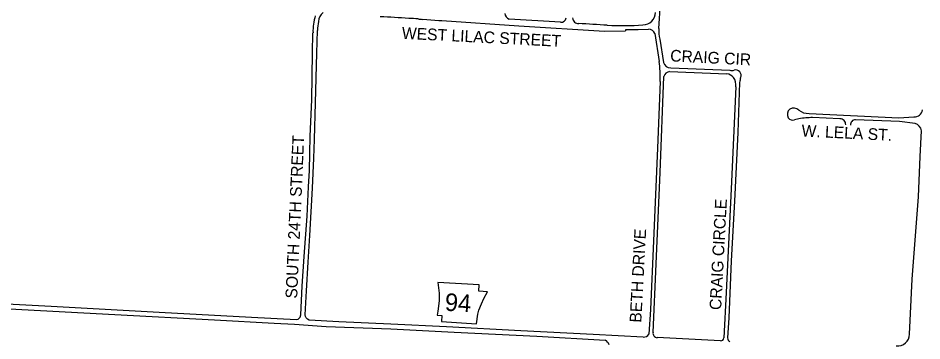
# Model space of a CAD drawing. Extents: x 0 to 712119, y 0 to 761125.
# Drawn here: x 676756 to 680612, y 727224 to 728604 of the extents above; entities that cross this region are included whole.
import ezdxf

# ---------------------------------------------------------------- set-up
doc = ezdxf.new("R2010")
doc.units = 0
for name, color, linetype in [('HWY signs', 7, 'Continuous'), ('PAVED ROADS', 7, 'Continuous'), ('street names', 7, 'Continuous')]:
    doc.layers.add(name, color=color, linetype=linetype)

msp = doc.modelspace()

# ---------------------------------------------------------------- linework, layer by layer
at = {"layer": 'HWY signs'}
msp.add_lwpolyline([(678711.4, 727298), (678717.8, 727338.3), (678722.5, 727356.1), (678732.8, 727382.8), (678743.5, 727405.2), (678758.3, 727434.3), (678721.3, 727436.5), (678723, 727463.9), (678547.5, 727474.5), (678553, 727428.9), (678552.4, 727395.8), (678546.9, 727351.5), (678543.9, 727334), (678564.1, 727332.7), (678562.6, 727306.9)], close=True, dxfattribs=at)
at = {"layer": 'PAVED ROADS'}
for points in [[(679495.5, 728670), (679495.5, 728667.5), (679489, 728559.5)], [(678482.5, 728598.5), (678551.5, 728594), (678563.5, 728593)], [(678563.5, 728593), (678892.5, 728570.5), (679258.5, 728548.5), (679348, 728550)], [(679069.6, 728585.9), (678851.9, 728599.7), (678851.9, 728599.7)], [(676708, 727383.5), (676897.5, 727373), (677358, 727347.5), (677751.5, 727325.5), (677944.5, 727315.5), (677951, 727317.5), (677955.5, 727321), (677960, 727326.5), (677962.5, 727336.5), (677969, 727458), (677977, 727585.5), (677990, 727757), (677995, 727883.5), (677999, 727952), (678001.5, 728025.5), (678003, 728099), (678009.5, 728254), (678012.5, 728455.5), (678014.5, 728541)], [(679423, 727240.5), (679210, 727251.5), (678901.5, 727267), (678584, 727284), (678346.5, 727295.5), (678125, 727306.5), (677998.5, 727313), (677991.5, 727317), (677985.5, 727322.5), (677982.1, 727328.6), (677981, 727336), (677987.5, 727438), (677994.5, 727561), (678000.8, 727674.7), (678012.2, 727876.7), (678017.5, 728005.6), (678021.1, 728085.3), (678025, 728241.1), (678030.2, 728454.1), (678033.7, 728550.7)], [(679401, 728555.5), (679446, 728556)], [(679472, 728537.5), (679490.5, 728419)], [(679493.4, 728513.7), (679510.3, 728414.5)], [(679540.5, 728391), (679792.6, 728381.1)], [(679464.9, 727260.6), (679477.7, 727554.1), (679495.8, 727944.7), (679511.6, 728354.4)], [(679535.8, 728375.2), (679779.8, 728365.8)], [(679495.4, 728333.4), (679483.9, 728047.8), (679466.3, 727652.4), (679454.1, 727359.2), (679447.2, 727254)], [(679817.6, 728309.8), (679798.5, 727874.1), (679777.6, 727432), (679766.9, 727237.3)], [(679834.5, 728328.5), (679827.1, 728114.7), (679812, 727821), (679799, 727567), (679788, 727323), (679783, 727237.5)], [(680130.4, 728196.3), (680513, 728177.5), (680577.5, 728181.5)], [(680087.5, 728173.5), (680069, 728169.5)], [(680261.9, 728173.2), (680145.5, 728178.9)], [(680583, 728153.5), (680516, 728161.5), (680328.5, 728169.5)], [(680559.5, 727252.8), (680570.5, 727488.5), (680598, 727840), (680605, 728013), (680610, 728122.5)], [(676711.5, 727361.5), (676719.5, 727362), (677169.5, 727337), (677595, 727314), (677849, 727300), (677936, 727295.5), (678070.6, 727286.7), (678347, 727275.5), (678616.5, 727262.5), (678969.5, 727244.5), (679260.2, 727227.4)], [(679753.2, 727224.7), (679482.5, 727238.4)]]:
    msp.add_lwpolyline(points, dxfattribs=at)
for centre, radius, start, end in [((678261.5, 728546), 247, 164.0165, 181.1542), ((678087.2, 728588.8), 48.7, 127.4801, 179.5185), ((678858.4, 728624.7), 25.8, 182.0128, 255.3103), ((679421.2, 728628.2), 53.7, 270.7156, 359.9515), ((678231.7, 728546.1), 198, 167.4147, 178.6567), ((678117.9, 724365.1), 4248.3, 85.882, 87.5234), ((678370.5, 727460.1), 1143.6, 85.387, 87.3701), ((678584.6, 730093.6), 1498.6, 265.3274, 266.0943), ((679072.2, 728608.8), 23.1, 263.6247, 348.6858), ((679146.9, 728605.3), 24.9, 182.198, 272.2362), ((678702.1, 719962.1), 8629.8, 86.22792, 87.03927), ((679332.8, 730192.6), 1620.6, 267.7724, 273.1502), ((679359.5, 728551), 11.5, 162.3499, 184.9697), ((679321, 731379.3), 2825, 270.5587, 271.6237), ((679446.9, 728529.8), 26.3, 17.1452, 91.9882), ((679686, 728555.5), 197, 178.8301, 192.2351), ((679074, 728352.1), 421.8, 357.4626, 9.1268), ((679539.8, 728421.3), 30.3, 192.9095, 271.3098), ((679818.1, 728359.6), 22.5, 332.7288, 108.7091), ((679537.6, 728348.6), 26.6, 93.7539, 167.6081), ((679770.4, 728313.1), 53.5, 43.9369, 79.8239), ((679802, 728420.2), 40.2, 256.4387, 282.7045), ((679767.3, 728320.2), 51.3, 348.3589, 35.7638), ((680844.3, 728164.4), 1023, 169.5919, 170.7723), ((680064.9, 728192.6), 27.4, 125.6981, 213.4413), ((680064.6, 728188.5), 30.7, 44.4945, 120.7648), ((680129.7, 728271), 74.7, 234.7184, 270.5795), ((680580.4, 728215.1), 33.7, 265.0058, 354.7596), ((680060.4, 728189.9), 22.1, 214.0113, 292.98), ((680154, 727770.8), 408.2, 91.1917, 99.3751), ((680262.8, 728149), 24.2, 357.5702, 92.1831), ((680328.5, 728148.4), 21.1, 90.0901, 185.115), ((680570.7, 728115.5), 39.9, 10.061, 72.0486), ((679248.4, 727198.8), 31, 17.294, 67.5896), ((679423.6, 727267.9), 27.4, 268.7804, 329.3952), ((679484, 727257.6), 19.3, 171.2434, 265.5063), ((679753.5, 727238.2), 13.4, 268.869, 356.1544), ((679798.4, 727236.9), 15.4, 177.874, 249.5061), ((680507.8, 727254.9), 51.7, 264.0644, 357.6927)]:
    msp.add_arc(centre, radius, start, end, dxfattribs=at)

# ---------------------------------------------------------------- texts
at = {"layer": 'HWY signs'}
msp.add_text('94', height=75, rotation=356.5521, dxfattribs=at).set_placement((678575.5, 727353.7))
at = {"layer": 'street names'}
for s, rotation, p in [('WEST LILAC STREET', 357.0768, (678392.5, 728515.6)), ('CRAIG CIR', 357.0768, (679537.3, 728419)), ('W. LELA ST.', 357.0768, (680097.5, 728098.6)), ('SOUTH 24TH STREET', 87.5032, (677946.8, 727404.6)), ('CRAIG CIRCLE', 86.9838, (679755.4, 727355.6)), ('BETH DRIVE', 86.9838, (679414.8, 727301.6))]:
    msp.add_text(s, height=50, rotation=rotation, dxfattribs=at).set_placement(p)

doc.saveas('drawing.dxf')
